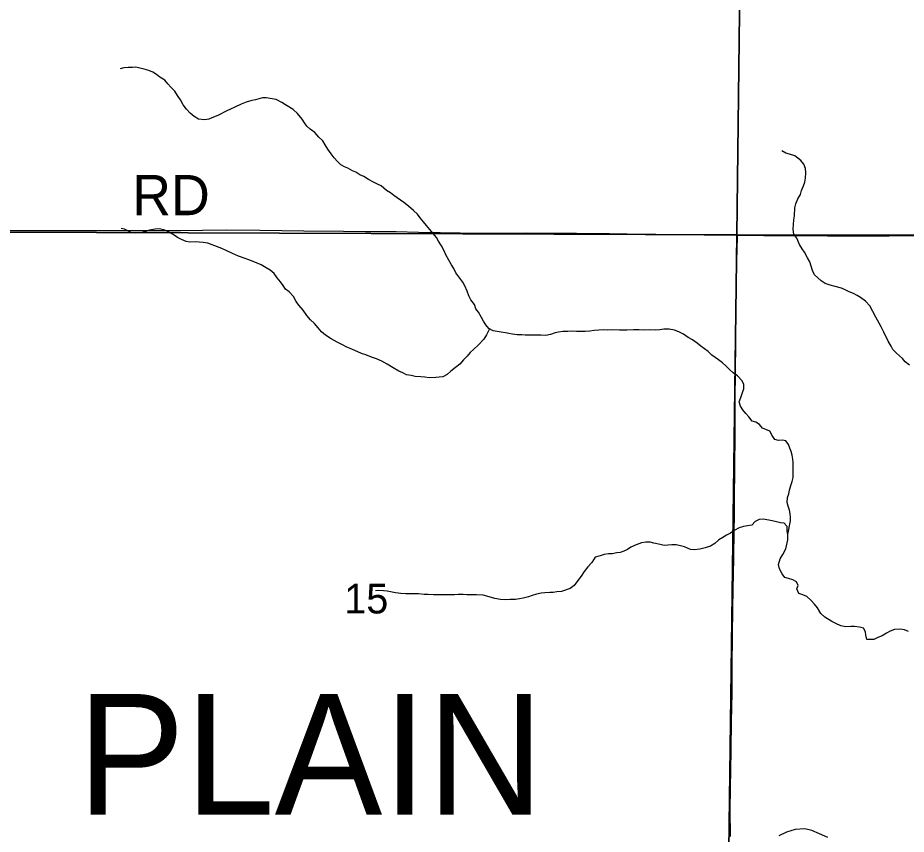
# Model space of a CAD drawing. Extents: x 1985906 to 2360102, y 891258 to 1222054.
# Drawn here: x 2092575 to 2099202, y 1010455 to 1016547 of the extents above; entities that cross this region are included whole.
import ezdxf

# ---------------------------------------------------------------- set-up
doc = ezdxf.new("R2010")
doc.units = 0
for name, color, linetype in [('GM_X_County_Road', 7, 'Continuous'), ('GM_X_County_Road_Text', 7, 'Continuous'), ('GM_X_Minor_River', 7, 'Continuous'), ('GM_X_Section', 7, 'Continuous'), ('GM_X_Section_Text', 7, 'Continuous'), ('GM_X_Township_Road', 7, 'Continuous'), ('GM_X_Township_Text', 7, 'Continuous')]:
    doc.layers.add(name, color=color, linetype=linetype)

msp = doc.modelspace()

# ---------------------------------------------------------------- linework, layer by layer
at = {"layer": 'GM_X_County_Road'}
for points in [[(2092477.1, 1014959.6), (2092772.6, 1014960.3), (2092936.7, 1014959.9), (2093035.2, 1014959.7), (2093166.4, 1014959.7), (2093330.4, 1014959.6), (2093510.9, 1014958.5), (2093790.1, 1014958.5), (2093954.2, 1014961.6), (2094134.6, 1014963.7), (2094380.8, 1014963), (2094544.8, 1014960.6), (2094709, 1014958), (2095004.3, 1014954.6), (2095168.4, 1014952.5), (2095397.1, 1014951.2), (2095562.9, 1014947.7), (2095725.9, 1014943.8), (2095873.6, 1014941.1), (2096103.5, 1014940.6), (2096366.1, 1014940.9), (2096645.1, 1014939.4), (2096743.5, 1014938.5), (2096989.6, 1014936.2), (2097120.9, 1014935.4), (2097334.3, 1014932.3), (2097498.4, 1014930.2), (2097695.3, 1014928.2), (2097943.1, 1014924.5)], [(2097943.1, 1014924.5), (2097957.9, 1014924.6), (2098138.5, 1014922.8), (2098236.9, 1014922.5), (2098368.1, 1014921.9), (2098466.5, 1014920.9), (2098614.2, 1014919.4), (2098778.3, 1014920.2), (2099073.6, 1014920.1), (2099401.8, 1014921.4), (2099500.2, 1014921.6), (2099631.4, 1014921.1), (2099844.7, 1014920.6), (2100041.6, 1014919.4), (2100626.9, 1014917.6)]]:
    msp.add_lwpolyline(points, dxfattribs=at)
at = {"layer": 'GM_X_Minor_River'}
for points in [[(2095980.5, 1014408), (2095954.2, 1014442), (2095940.1, 1014472), (2095925.8, 1014506.1), (2095909.6, 1014546.2), (2095895.4, 1014574.2), (2095873.2, 1014604.2), (2095843, 1014644.2), (2095828.8, 1014676.3), (2095810.6, 1014704.3), (2095790.4, 1014738.4), (2095768.1, 1014778.4), (2095755.9, 1014808.5), (2095735.7, 1014844.5), (2095713.5, 1014880.5), (2095697.3, 1014906.6), (2095648.9, 1014966.6), (2095622.7, 1014996.6), (2095602.5, 1015024.6), (2095576.3, 1015054.6), (2095556.1, 1015080.6), (2095525.9, 1015108.5), (2095489.7, 1015140.5), (2095453.5, 1015168.4), (2095381, 1015220.3), (2095354.9, 1015240.3), (2095324.7, 1015258.2), (2095284.5, 1015292.2), (2095258.4, 1015304.1), (2095228.2, 1015320), (2095190, 1015339.9), (2095155.9, 1015361.8), (2095125.7, 1015373.7), (2095097.6, 1015393.7), (2095071.5, 1015405.6), (2095037.3, 1015423.5), (2095011.2, 1015435.4), (2094985.1, 1015449.4), (2094958.9, 1015475.4), (2094934.7, 1015501.3), (2094912.5, 1015531.3), (2094888.3, 1015565.4), (2094868.1, 1015597.4), (2094849.9, 1015627.4), (2094821.7, 1015655.4), (2094791.4, 1015689.4), (2094757.2, 1015715.3), (2094731.1, 1015737.3), (2094714.9, 1015763.3), (2094696.7, 1015789.3), (2094662.5, 1015831.3), (2094628.2, 1015861.3), (2094571.9, 1015897.2), (2094545.8, 1015915.1), (2094501.6, 1015937), (2094473.5, 1015942.9), (2094427.4, 1015948.7), (2094401.3, 1015948.6), (2094347.3, 1015934.3), (2094321.3, 1015930.2), (2094279.3, 1015915.9), (2094241.3, 1015901.7), (2094195.3, 1015879.4), (2094161.3, 1015865.2), (2094135.3, 1015851), (2094067.4, 1015816.6), (2094035.4, 1015804.4), (2093999.4, 1015790.2), (2093969.4, 1015784), (2093923.2, 1015789.8), (2093891.1, 1015809.8), (2093860.9, 1015835.7), (2093834.7, 1015863.7), (2093808.4, 1015897.7), (2093788.2, 1015933.8), (2093766, 1015967.8), (2093745.8, 1015997.8), (2093717.6, 1016027.8), (2093693.4, 1016053.8), (2093671.2, 1016079.8), (2093635, 1016103.7), (2093608.9, 1016123.7), (2093582.7, 1016139.6), (2093552.6, 1016153.5), (2093518.5, 1016163.4), (2093486.4, 1016171.3), (2093456.3, 1016177.2), (2093430.3, 1016175), (2093398.2, 1016174.9), (2093366.1, 1016172.7), (2093338.1, 1016164.6)], [(2098974.7, 1014313.3), (2098930.2, 1014397.4), (2098897.9, 1014433.4), (2098861.7, 1014459.3), (2098835.6, 1014475.2), (2098807.5, 1014489.2), (2098777.3, 1014501.1), (2098745.2, 1014517), (2098719.1, 1014528.9), (2098672.9, 1014542.8), (2098634.8, 1014552.6), (2098596.7, 1014564.5), (2098568.5, 1014584.4), (2098518.2, 1014628.4), (2098502, 1014660.4), (2098483.6, 1014724.6), (2098465.4, 1014756.6), (2098443.1, 1014796.7), (2098425, 1014822.7), (2098406.8, 1014854.7), (2098386.5, 1014902.8), (2098364.3, 1014932.8), (2098358.1, 1014968.9), (2098359.9, 1015005.1), (2098363.7, 1015039.2), (2098367.6, 1015069.3), (2098371.3, 1015129.6), (2098379.1, 1015157.7), (2098393, 1015195.9), (2098412.8, 1015228.2), (2098420.7, 1015258.3), (2098436.5, 1015292.5), (2098444.4, 1015320.6), (2098450.3, 1015350.8), (2098452.1, 1015388.9), (2098449.9, 1015423), (2098437.7, 1015453.1), (2098415.5, 1015481.1), (2098371.2, 1015517), (2098331.1, 1015528.9), (2098303, 1015536.8), (2098274.8, 1015554.8)], [(2096092.3, 1014226.2), (2096091.6, 1014221.8), (2096071.8, 1014181.5), (2096052, 1014149.3), (2096008.1, 1014105), (2095976.2, 1014074.7), (2095950.3, 1014048.5), (2095926.4, 1014022.3), (2095900.5, 1013994.1), (2095872.6, 1013961.8), (2095840.7, 1013937.6), (2095804.7, 1013909.3), (2095778.8, 1013885.1), (2095744.8, 1013868.9), (2095718.8, 1013864.8), (2095692.8, 1013862.6), (2095642.7, 1013860.4), (2095610.6, 1013864.3), (2095582.5, 1013868.2), (2095540.4, 1013870), (2095510.3, 1013877.8), (2095474.2, 1013883.7), (2095448.1, 1013897.6), (2095418, 1013909.5), (2095375.8, 1013935.5), (2095331.5, 1013963.4), (2095289.4, 1013985.2), (2095251.2, 1014001.1), (2095213, 1014015), (2095170.9, 1014030.9), (2095138.8, 1014042.8), (2095110.6, 1014054.7), (2095072.5, 1014070.6), (2095024.3, 1014092.4), (2094998.2, 1014106.4), (2094958, 1014126.3), (2094911.7, 1014152.2), (2094871.5, 1014178.1), (2094841.3, 1014204), (2094815.1, 1014234), (2094788.9, 1014266), (2094758.7, 1014294), (2094730.5, 1014326), (2094704.2, 1014364), (2094672, 1014402), (2094651.8, 1014430), (2094631.6, 1014466.1), (2094599.3, 1014502.1), (2094573.2, 1014522), (2094555, 1014550), (2094534.8, 1014576), (2094510.6, 1014606), (2094486.4, 1014638.1), (2094458.2, 1014664), (2094428, 1014682), (2094389.8, 1014703.9), (2094343.7, 1014723.7), (2094297.5, 1014741.6), (2094271.4, 1014749.5), (2094221.2, 1014767.3), (2094177, 1014787.2), (2094130.8, 1014809.1), (2094096.6, 1014825), (2094024.4, 1014852.8), (2093992.2, 1014864.7), (2093958.1, 1014870.5), (2093928.1, 1014872.4), (2093900, 1014874.3), (2093857.9, 1014872.1), (2093831.8, 1014878), (2093795.7, 1014891.9), (2093765.6, 1014907.8), (2093735.4, 1014929.8), (2093701.2, 1014947.7), (2093673.1, 1014961.6), (2093633, 1014971.4), (2093600.9, 1014969.3), (2093558.9, 1014961.1), (2093524.9, 1014948.9), (2093490.8, 1014942.7), (2093450.8, 1014940.5), (2093424.7, 1014942.4), (2093372.5, 1014970.2), (2093346.4, 1014974.2)], [(2098317.9, 1012692.2), (2098339.4, 1012792.7), (2098339.3, 1012820.8), (2098337.2, 1012846.8), (2098331, 1012872.9), (2098320.8, 1012903), (2098312.7, 1012931.1), (2098316.5, 1012967.2), (2098326.4, 1012995.4), (2098332.2, 1013021.5), (2098342.1, 1013057.7), (2098351.9, 1013087.8), (2098357.8, 1013116), (2098357.6, 1013152.1), (2098359.3, 1013202.3), (2098359.2, 1013228.4), (2098355.1, 1013254.5), (2098350.9, 1013282.5), (2098344.7, 1013310.6), (2098334.6, 1013336.7), (2098322.4, 1013362.7), (2098304.2, 1013390.8), (2098278.2, 1013394.6), (2098248.1, 1013392.5), (2098222, 1013400.4), (2098201.8, 1013430.4), (2098185.6, 1013462.5), (2098155.5, 1013474.4), (2098129.4, 1013484.3), (2098107.2, 1013512.3), (2098079.1, 1013530.2), (2098053, 1013536.2), (2098026.8, 1013568.2), (2098006.6, 1013594.2), (2097982.4, 1013622.2), (2097966.3, 1013648.2), (2097956.1, 1013680.2), (2097967.9, 1013714.4), (2097981.7, 1013750.6), (2097991.6, 1013778.8), (2097991.4, 1013810.9), (2097979.3, 1013839), (2097943, 1013874.9), (2097910.8, 1013896.9), (2097884.7, 1013922.8), (2097856.5, 1013950.8), (2097830.3, 1013972.8), (2097802.1, 1013994.7), (2097751.8, 1014030.6), (2097723.7, 1014056.6), (2097697.5, 1014076.6), (2097669.3, 1014096.5), (2097643.2, 1014118.5), (2097607, 1014144.4), (2097574.8, 1014162.3), (2097540.6, 1014186.2), (2097504.5, 1014202.2), (2097472.3, 1014216), (2097434.2, 1014223.9), (2097394.1, 1014223.7), (2097364.1, 1014219.6), (2097330.1, 1014215.4), (2097284, 1014217.2), (2097247.9, 1014217), (2097209.8, 1014218.9), (2097167.7, 1014218.7), (2097117.7, 1014216.4), (2097063.5, 1014216.2), (2097009.4, 1014218), (2096975.4, 1014215.8), (2096943.3, 1014217.7), (2096909.3, 1014215.5), (2096873.2, 1014213.3), (2096841.2, 1014209.2), (2096807.1, 1014205), (2096779.1, 1014204.9), (2096743, 1014206.7), (2096714.9, 1014208.6), (2096678.9, 1014206.4), (2096640.8, 1014206.2), (2096608.8, 1014200.1), (2096582.7, 1014195.9), (2096548.7, 1014183.7), (2096512.7, 1014175.5), (2096476.6, 1014177.4), (2096450.6, 1014179.3), (2096360.4, 1014178.9), (2096334.3, 1014180.7), (2096300.3, 1014180.6), (2096264.2, 1014186.4), (2096238.1, 1014190.3), (2096212, 1014196.2), (2096179.9, 1014202.1), (2096119.8, 1014209.9), (2096089.6, 1014227.8), (2096065.4, 1014255.8), (2096049.2, 1014283.8), (2096035.1, 1014309.9), (2096010.8, 1014349.9), (2095990.6, 1014375.9), (2095980.5, 1014408)], [(2099227, 1013955.1), (2099194.9, 1013979), (2099172.7, 1014005), (2099128.4, 1014045), (2099102.2, 1014070.9), (2099090, 1014097), (2099067.8, 1014135), (2099035.4, 1014201.1), (2099015.1, 1014241.2), (2098999, 1014267.2), (2098974.7, 1014313.3)], [(2098317.9, 1012692.2), (2098313.8, 1012718.3), (2098313.6, 1012750.4), (2098291.4, 1012776.4), (2098263.4, 1012778.3), (2098235.3, 1012786.2), (2098201.2, 1012794), (2098137, 1012805.8), (2098104.9, 1012803.6), (2098075, 1012789.4), (2098049.1, 1012761.2), (2098019, 1012757.1), (2097989, 1012750.9), (2097955, 1012740.7), (2097919, 1012720.5), (2097891.1, 1012700.3), (2097861.1, 1012686.1), (2097833.1, 1012667.9), (2097805.2, 1012651.7), (2097775.3, 1012623.4), (2097741.3, 1012605.2), (2097703.3, 1012591), (2097661.3, 1012580.8), (2097621.2, 1012576.6), (2097593.1, 1012580.5), (2097546.9, 1012600.3), (2097518.9, 1012606.2), (2097486.8, 1012614.1), (2097452.7, 1012613.9), (2097422.6, 1012611.8), (2097396.6, 1012609.7), (2097366.5, 1012617.6), (2097320.4, 1012627.4), (2097292.3, 1012633.3), (2097260.2, 1012635.1), (2097226.2, 1012629), (2097188.2, 1012614.7), (2097148.2, 1012596.5), (2097122.2, 1012580.3), (2097094.3, 1012566.1), (2097068.3, 1012558), (2097042.2, 1012553.8), (2097008.2, 1012547.7), (2096980.1, 1012547.5), (2096948.1, 1012543.4), (2096918.1, 1012533.2), (2096882.1, 1012523), (2096856.2, 1012482.7), (2096826.4, 1012450.5), (2096798.5, 1012414.2), (2096776.6, 1012380), (2096752.7, 1012347.8), (2096724.9, 1012311.5), (2096694.9, 1012289.3), (2096630.9, 1012266.9), (2096594.9, 1012262.7), (2096568.9, 1012258.6), (2096542.8, 1012258.5), (2096506.8, 1012256.3), (2096478.7, 1012254.2), (2096444.7, 1012246), (2096410.7, 1012235.8), (2096384.7, 1012225.6), (2096344.7, 1012215.4), (2096316.6, 1012211.2), (2096286.6, 1012207.1), (2096246.5, 1012206.9), (2096212.5, 1012204.8), (2096174.4, 1012206.6), (2096134.3, 1012214.4), (2096092.1, 1012226.3), (2096046, 1012238.1), (2095995.9, 1012241.9), (2095923.7, 1012241.6), (2095897.7, 1012243.5), (2095859.6, 1012243.3), (2095831.5, 1012241.2), (2095725.3, 1012240.7), (2095675.2, 1012242.4), (2095637.2, 1012244.3), (2095607.1, 1012244.2), (2095565, 1012248), (2095536.9, 1012247.8), (2095508.9, 1012249.7), (2095470.8, 1012249.5), (2095432.7, 1012251.4), (2095392.6, 1012257.2), (2095366.5, 1012261.1), (2095330.4, 1012269), (2095302.4, 1012270.9), (2095262.3, 1012272.7), (2095244, 1012270.3)], [(2099217.4, 1011967.6), (2099189.3, 1011979.5), (2099157.2, 1011985.3), (2099115.2, 1011983.2), (2099081.2, 1011970.9), (2099055.2, 1011954.8), (2099021.2, 1011934.5), (2098989.3, 1011922.3), (2098959.3, 1011908.2), (2098907.2, 1011907.9), (2098901, 1011940), (2098898.8, 1011966.1), (2098882.7, 1011992.1), (2098852.6, 1012000), (2098816.5, 1012005.9), (2098788.4, 1012005.8), (2098752.4, 1012003.6), (2098714.3, 1012009.4), (2098676.1, 1012027.3), (2098646, 1012043.2), (2098595.7, 1012075.1), (2098565.5, 1012103.1), (2098539.2, 1012145.1), (2098517, 1012171.1), (2098492.8, 1012199.1), (2098460.6, 1012229.1), (2098430.5, 1012241), (2098400.4, 1012250.9), (2098386.2, 1012285), (2098396.1, 1012311.1), (2098383.9, 1012337.2), (2098355.8, 1012353.1), (2098323.7, 1012363), (2098295.6, 1012370.9), (2098277.4, 1012398.9), (2098257.2, 1012434.9), (2098249, 1012467), (2098260.8, 1012509.2), (2098280.7, 1012541.4), (2098302.5, 1012585.7), (2098318.1, 1012652), (2098317.9, 1012692.2)], [(2098618, 1010429.8), (2098555.9, 1010459.5), (2098497.7, 1010483.2), (2098445.7, 1010494.9), (2098373.7, 1010490.5), (2098309.8, 1010470.1), (2098252, 1010443.7)]]:
    msp.add_lwpolyline(points, dxfattribs=at)
at = {"layer": 'GM_X_Section'}
for points in [[(2098003.5, 1020315.5), (2097937.6, 1014926.1), (2092482.4, 1014947.7), (2092534.2, 1020341)], [(2103278.8, 1020259), (2103292.7, 1014922), (2097937.6, 1014926.1), (2098003.5, 1020315.5)], [(2092482.4, 1014947.7), (2097937.6, 1014926.1), (2097869.4, 1009570.8), (2092452.1, 1009640.6)], [(2097937.6, 1014926.1), (2103292.7, 1014922), (2103254.4, 1009592.8), (2097869.4, 1009570.8)]]:
    msp.add_lwpolyline(points, close=True, dxfattribs=at)
at = {"layer": 'GM_X_Township_Road'}
msp.add_lwpolyline([(2097889.9, 1010438.8), (2097889.8, 1010635.6), (2097891.6, 1010799.6), (2097896.6, 1011078.5), (2097899.4, 1011308), (2097901, 1011390), (2097902.8, 1011521.1), (2097904.4, 1011717.9), (2097909.1, 1012144.3), (2097914.2, 1012406.7), (2097914.9, 1012505), (2097918.2, 1012734.1), (2097919.9, 1012816), (2097921.3, 1012914.4), (2097921.9, 1013012.7), (2097922.6, 1013127.4), (2097923.9, 1013274.9), (2097924.7, 1013356.9), (2097925.3, 1013455.2), (2097926.1, 1013569.9), (2097926.9, 1013717.5), (2097928.4, 1013881.6), (2097930.2, 1014144), (2097931.5, 1014275.1), (2097935.2, 1014504.3), (2097937, 1014602.7), (2097940.1, 1014832.4), (2097942.3, 1014897.9), (2097943.1, 1014924.5)], dxfattribs=at)

# ---------------------------------------------------------------- texts
at = {"layer": 'GM_X_County_Road_Text'}
msp.add_text('RD', height=300, rotation=0.00001, dxfattribs=at).set_placement((2093428.2, 1015073.6))
at = {"layer": 'GM_X_Section_Text'}
msp.add_text('15', height=221, rotation=0.00001, dxfattribs=at).set_placement((2095010, 1012102.4))
at = {"layer": 'GM_X_Township_Text'}
msp.add_text('PLAIN', height=900, rotation=0.00001, dxfattribs=at).set_placement((2093019.3, 1010601.1))

doc.saveas('drawing.dxf')
